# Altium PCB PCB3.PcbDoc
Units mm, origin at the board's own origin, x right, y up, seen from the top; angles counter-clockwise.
Board outline 20 x 20 mm, 2 copper layers (Top Layer, Bottom Layer); 3 components, 14 nets, 31 pads, 0 vias.
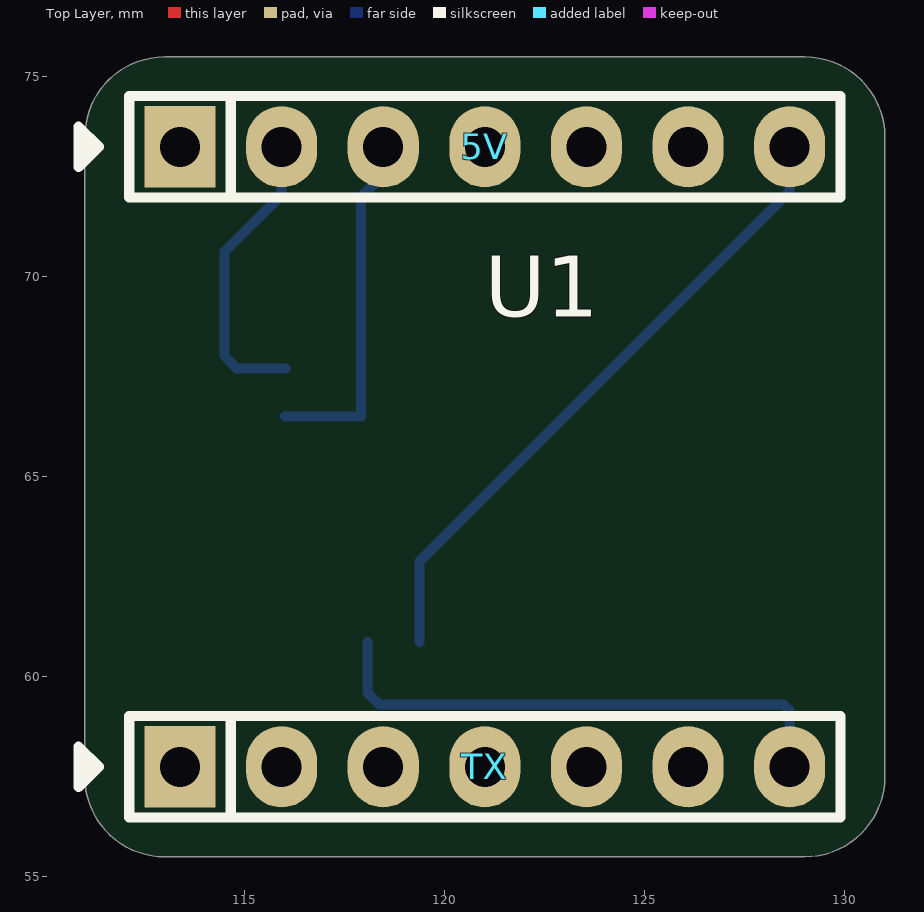
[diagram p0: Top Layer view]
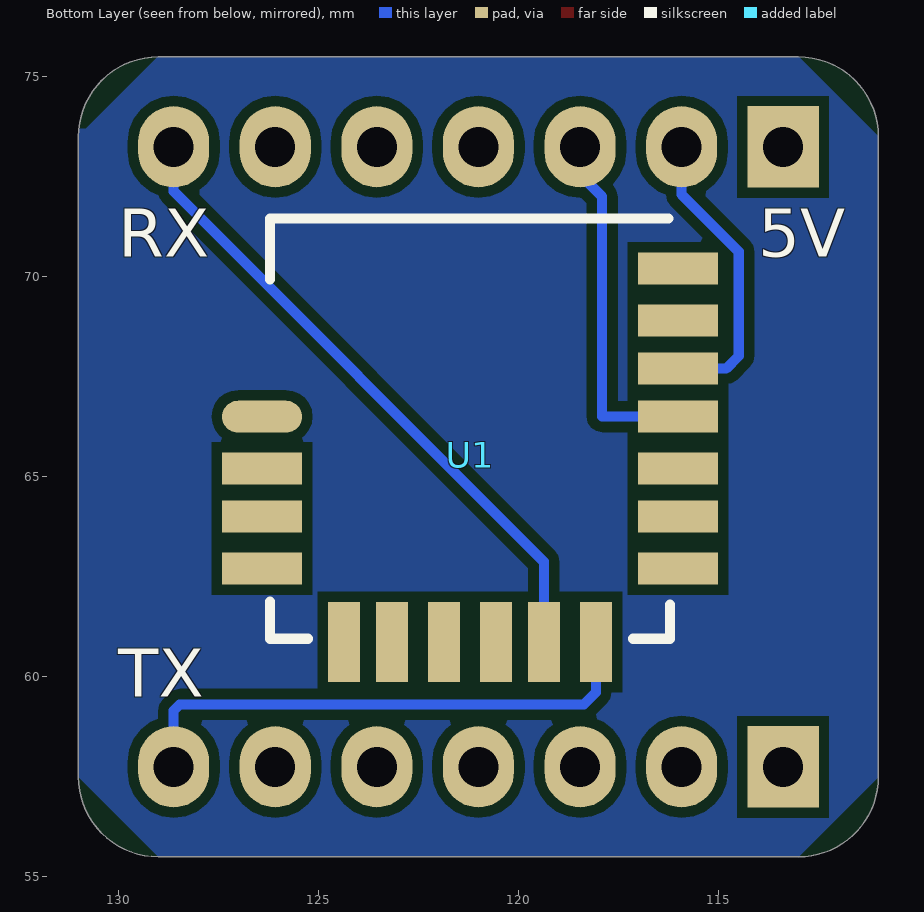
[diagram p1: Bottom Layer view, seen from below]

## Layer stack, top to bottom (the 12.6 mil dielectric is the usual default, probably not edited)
Top Solder: solder mask 0.0102, Solder Resist, Dk 3.5
Top Layer: signal copper 0.0356
Dielectric 1: dielectric 0.32, FR-4, Dk 4.8
Bottom Layer: signal copper 0.0356
Bottom Solder: solder mask 0.0102, Solder Resist, Dk 3.5

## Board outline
111,57.5 111,73.5 cw(c113,73.5) 113,75.5 129,75.5 cw(c129,73.5) 131,73.5 131,57.5 cw(c129,57.5) 129,55.5 113,55.5 cw(c113,57.5)

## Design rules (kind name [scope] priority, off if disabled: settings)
Clearance [All] p1: gap=0.254
PolygonConnect [All] p1: connectstyle=Relief reliefconductorwidth=0.254 reliefentries=4 polygonreliefangle="90 Angle" airgapwidth=0.254
RoutingVias [All] p1: holewidth=0.711 width=1.27 viastyle="Through Hole" minholewidth=0.711 minwidth=1.27 maxholewidth=0.711 maxwidth=1.27
SolderMaskExpansion [All] p1: expansion=0.102
Width [All] p1: maxlimit=0.254 minlimit=0.254 preferedwidth=0.254
29 further rules are at their usual default settings.

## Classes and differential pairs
component class Sheet3: U1

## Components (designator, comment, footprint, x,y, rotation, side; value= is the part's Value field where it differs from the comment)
5V "HDR1x7" PIN-7-2.54-1.0 121,73.25 r0 top (schematic designator J2)
TX "HDR1x7" PIN-7-2.54-1.0 121,57.75 r0 top (schematic designator J1)
U1 "WH-BLE103" PCBComponent_1 -225.58,905.5 r180 bottom

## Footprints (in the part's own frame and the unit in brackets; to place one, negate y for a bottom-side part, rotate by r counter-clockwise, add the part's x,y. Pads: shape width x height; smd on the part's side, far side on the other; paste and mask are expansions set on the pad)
PCBComponent_1 [mm]
  oval 2x0.8 smd: 1(-351.99,-838.996)
  rect 2x0.8 smd: 2(-351.99,-840.296) 3(-351.99,-841.496) 4(-351.99,-842.796) 11(-341.59,-842.796) 12(-341.59,-841.496) 13(-341.59,-840.296) 14(-341.59,-838.996) 15(-341.59,-837.796) 16(-341.59,-836.596) 17(-341.59,-835.296)
  rect 0.8x2 smd: 5(-349.944,-844.632) 6(-348.744,-844.632) 7(-347.444,-844.632) 8(-346.144,-844.632) 9(-344.944,-844.632) 10(-343.644,-844.632)
  silkscreen extent -351.79,-844.55 -341.79,-834.04
PIN-7-2.54-1.0 [mil] "Pin Header"
  rect 70x80 hole 39.37: 1(-300,0)
  oval 70x80 hole 39.37: 2(-200,0) 3(-100,0) 4(0,0) 5(100,0) 6(200,0) 7(300,0)
  silkscreen extent -400,-50 350,50, body extent -350,-50 350,50, height 398

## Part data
5V TX: "Connector"

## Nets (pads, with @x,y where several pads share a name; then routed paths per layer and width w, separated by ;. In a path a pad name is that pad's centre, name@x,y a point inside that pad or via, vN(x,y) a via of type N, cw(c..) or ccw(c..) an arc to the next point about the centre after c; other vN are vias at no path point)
3.3V: 5V.3 U1.14 | length 8.9
  Bottom Layer w0.254: U1.14 117.908,66.504 117.908,72 118.46,72.552 5V.3
5V: 5V.1
D0: TX.1
D1: TX.2
D2: TX.3
D3: TX.4
D4: TX.5
D5: TX.6
D8: 5V.6
D9: 5V.5
D10: 5V.4
GND: 5V.2 U1.15 | length 7.5
  Bottom Layer w0.254: 5V.2 115.92,72.054 114.49,70.624 114.49,68.022 114.808,67.704 U1.15
RX: 5V.7 U1.9 | length 16.2
  Bottom Layer w0.254: U1.9 119.364,62.88 128.62,72.136 5V.7
TX: TX.7 U1.10 | length 13.4
  Bottom Layer w0.254: U1.10 118.064,59.609 118.364,59.309 128.468,59.309 128.62,59.157 TX.7
pads on no net: U1.1 U1.2 U1.3 U1.4 U1.5 U1.6 U1.7 U1.8 U1.11 U1.12 U1.13 U1.16 U1.17

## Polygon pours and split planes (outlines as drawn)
no net on Bottom Layer "Top Layer-No Net" (solid, pour order 2): 110.995,73.5 112.995,75.5 113,75.5 128.99,75.5 129,75.51 130.814,73.696 130.99,73.696 130.99,57.51 131,57.5 129,55.5 113.01,55.5 113,55.49 110.995,57.495 110.995,57.5 110.995,73.495 110.99,73.5

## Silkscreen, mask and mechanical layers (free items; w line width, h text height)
Bottom Overlay:
  text "RX" at 130,70.5 h1.2
Mechanical 1:
  lines w0.254: 111,57.5 ccw(c113,57.5) 113,55.5 129,55.5 ccw(c129,57.5) 131,57.5 131,73.5 ccw(c129,73.5) 129,75.5 125,75.5 113,75.5 ccw(c113,73.5) 111,73.5 111,57.5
